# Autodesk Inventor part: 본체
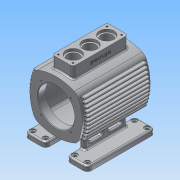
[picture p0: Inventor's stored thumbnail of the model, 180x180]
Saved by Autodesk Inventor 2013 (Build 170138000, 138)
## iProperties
Created: 2015-11
Part Number: 본체
Material: 알루미늄 6061
Document SubType Name: Modeling
Designer: mduedu
Density: 2.71 g/cm^3
Mass: 1542.18 g
Surface Area: 1694.57 cm^2
Volume: 569.07 cm^3
Author: mduedu
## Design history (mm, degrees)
sketch "스케치2"
  geometry: L1 (0, 250)-(0, -250); L2 (250, 0)-(-250, 0); L3 (-50, 50)-(50, 50); L4 (50, 50)-(50, -50); L5 (50, -50)-(-50, -50); L6 (-50, -50)-(-50, 50); A1 r 90 centre (-40, 0) between (40.415, -40.415) and (40.415, 40.415); A2 r 90 centre (40, 0) between (-40.415, 40.415) and (-40.415, -40.415); A3 r 90 centre (0, -40) between (40.415, 40.415) and (-40.415, 40.415); A4 r 90 centre (0, 40) between (-40.415, -40.415) and (40.415, -40.415); 2 further points
  constraints: 12 end point, 8 point on circle, 4 centre point, 4 tangent, 3 perpendicular, 2 horizontal alignment, 2 midpoint, 2 parallel, 2 symmetric about line, 1 coincident, 1 equal radius, 1 horizontal, 1 vertical, 1 vertical alignment, 2 other
  dimensions: "d6" = 500 distance of L1.start L1.end; "d8" = 500 distance of L2.start L2.end; "d9" = 100 distance of L3.end L4.end; "d11" = 90 radius of A3
extrude "돌출1" new body sketch "스케치2" stored distance "d12" = 130; taper "d13" = 0 deg
sketch "스케치3"
  geometry: A1 r 90 centre (40, 0) between (-40.415, 40.415) and (-40.415, -40.415) reference; 2 further points
  constraints: 1 point on circle
fillet "모깎기6" dims "d30" = 15
feature "쉘1" dims "d31" = 15, "d32" = 6, "d33" = 15
sketch "스케치4"
  geometry: L1 (60, -57)-(-60, -57); L2 (-65, 40.415)-(-65, -40.415) reference; L3 (65, -40.415)-(65, 40.415) reference; L4 (-60, -57)-(-60, -45); L5 (60, -57)-(60, -45); L6 (-65, -50)-(65, -50) reference; L7 (-60, -45)-(60, -45); 2 further points
  constraints: 8 end point, 2 parallel, 1 horizontal
  dimensions: "d16" = 5 distance between parallel lines of L7 L6; "d17" = 12 distance of L1.start L5.end; "d23" = 5 distance between parallel lines of L4 L2; "d24" = 5 distance between parallel lines of L5 L3
extrude "돌출2" new body sketch "스케치4" stored distance "d18" = 3; taper "d19" = 0 deg
fillet "모깎기1" dims "d20" = 3
fillet "모깎기4" dims "d25" = 1
sketch "스케치5"
  geometry: C1 r 35 at (0, 0); 1 further point
  constraints: 1 centre point, 1 coincident
  dimensions: "d34" = 70 diameter of C1
extrude "돌출3" cut sketch "스케치5" stored distance "d36" = 3; taper "d37" = 0 deg
feature "결합1"
  node "솔리드2"
fillet "모깎기7" dims "d38" = 1
fillet "모깎기8" dims "d39" = 1
node "작업 평면1"
sketch "스케치6"
  geometry: L1 (-65, -60)-(65, -60); L2 (65, -60)-(65, 60); L3 (65, 60)-(-65, 60); L4 (-65, 60)-(-65, -60); L5 (-65, -60)-(65, 60); L6 (65, -60)-(-65, 60); 1 further point
  constraints: 12 end point, 2 midpoint, 2 parallel, 1 horizontal, 1 perpendicular
  dimensions: "d41" = 120 distance of L3.end L1.start; "d43" = 130 distance of L2.end L3.end
extrude "돌출4" join sketch "스케치6" distance "d44" = 10; taper "d45" = 0 deg
sketch "스케치8"
  geometry: L1 (-60, -70)-(60, -70) reference; L2 (0, -50)-(0, -70); L3 (-30, -44.853)-(-30, -70); L4 (30, -44.853)-(30, -70); L5 (-30, -70)-(30, -70); A1 r 90 centre (0, 40) between (-34.941, -42.941) and (34.941, -42.941) reference; A2 r 90 centre (0, 40) between (-30, -44.853) and (30, -44.853); 1 further point
  constraints: 8 end point, 5 point on circle, 2 perpendicular, 2 symmetric about line, 1 centre point, 1 midpoint, 1 point on line
  dimensions: "d48" = 60 distance between parallel lines of L4 L3
extrude "돌출5" join sketch "스케치8" stored distance "d50" = 80; taper "d51" = 0 deg
sketch "스케치9"
  geometry: L1 (-30, -44.853)-(-30, -70) reference; L2 (30, -70)-(30, -44.853) reference; L3 (-20, -47.75)-(-20, -80); L4 (20, -80)-(20, -47.75); L5 (-48.917, -80)-(48.917, -80) reference; A1 r 90 centre (0, 40) between (-34.941, -42.941) and (34.941, -42.941) reference; 1 further point
  constraints: 4 end point, 2 parallel, 2 point on circle, 2 point on line
  dimensions: "d52" = 10 distance between parallel lines of L2 L4; "d54" = 10 distance between parallel lines of L1 L3 (derived)
extrude "돌출6" cut sketch "스케치9" stored distance "d55" = 80; taper "d56" = 0 deg
fillet "모깎기9" dims "d57" = 8
sketch "스케치10"
  geometry: A1 r 8 centre (-57, 52) between (-57, 60) and (-65, 52) reference; A2 r 8 centre (57, 52) between (65, 52) and (57, 60) reference; A3 r 8 centre (57, 28) between (57, 20) and (65, 28) reference; A4 r 8 centre (-57, 28) between (-65, 28) and (-57, 20) reference; A5 r 8 centre (-57, -28) between (-57, -20) and (-65, -28) reference; A6 r 8 centre (-57, -52) between (-65, -52) and (-57, -60) reference; A7 r 8 centre (57, -52) between (57, -60) and (65, -52) reference; A8 r 8 centre (57, -28) between (65, -28) and (57, -20) reference; 1 further point
hole "구멍1" sketch "스케치10" at (-57, 52), (57, 52), (57, 28), (-57, 28), (-57, -28), (-57, -52), (57, -52), (57, -28) diameter "d58" = 6; stored, may be unused: countersink angle "d62" = 90 deg, drill point angle "d64" = 118 deg; dims "d59" = 6, "d60" = 10, "d61" = 2, "d63" = 8
fillet "모깎기10" dims "d65" = 3
fillet "모깎기11" dims "d66" = 3
fillet "모깎기12" dims "d67" = 3
sketch "스케치11" dims "d72" = 25
  geometry: L1 (65, -50)-(-65, -50) reference; L2 (-80.5, -80)-(80.5, -80) reference; L3 (0, -50)-(0, -80); L4 (-27, -54)-(-10, -54); L5 (-10, -54)-(-10, -62); L6 (-10, -62)-(-27, -62); L7 (-27, -62)-(-27, -54); 3 further points
  constraints: 10 end point, 4 midpoint, 2 parallel, 2 perpendicular, 2 vertical alignment, 1 horizontal, 4 other
  dimensions: "d68" = 8 distance between parallel lines of L6 L4; "d71" = 8 distance from line of point (-27, -58) L1; "d73" = 6 dimension on L3
extrude "돌출7" cut sketch "스케치11" stored distance "d74" = 80; taper "d75" = 0 deg
fillet "모깎기13" dims "d76" = 3
fillet "모깎기14" dims "d78" = 3
sketch "스케치12"
  geometry: L1 (0, 0)-(28.284, 28.284); L2 (0, 0)-(40, 0); A1 r 40 centre (0, 0) between (28.284, 28.284) and (40, 0); 2 further points
  constraints: 4 end point, 2 coincident, 2 point on circle, 1 centre point, 1 horizontal
  dimensions: "d79" = 80 diameter of A1; "d80" = 45 deg angle of L2 L1
hole "구멍2" sketch "스케치12" at (28.284, 28.284) diameter "d82" = 3.242; stored, may be unused: countersink angle "d86" = 90 deg, drill point angle "d88" = 118 deg; dims "d83" = 9, "d84" = 10, "d85" = 2, "d87" = 11
node "작업 평면2"
sketch "스케치13"
  geometry: L1 (-52.5, -20)-(52.5, -20); L2 (52.5, -20)-(52.5, 20); L3 (52.5, 20)-(-52.5, 20); L4 (-52.5, 20)-(-52.5, -20); L5 (-52.5, -20)-(52.5, 20); L6 (52.5, -20)-(-52.5, 20); 1 further point
  constraints: 12 end point, 2 midpoint, 2 parallel, 1 horizontal, 1 perpendicular
  dimensions: "d93" = 105 distance of L2.end L3.end; "d95" = 40 distance of L1.end L2.end
extrude "돌출8" join sketch "스케치13" stored distance "d96" = 80; taper "d97" = 0 deg
fillet "모깎기15" dims "d98" = 5
fillet "모깎기16" dims "d99" = 3
sketch "스케치14"
  geometry: L1 (-52.5, 15)-(-52.5, -15) reference; L2 (52.5, -15)-(52.5, 15) reference; L3 (-52.5, 0)-(52.5, 0); 4 further points
  constraints: 2 end point, 2 midpoint, 2 point on line, 1 coincident
  dimensions: "d100" = 32 distance of point (-32, 0) point (0, 0); "d102" = 32 distance of point (32, 0) point (0, 0) (derived)
hole "구멍3" sketch "스케치14" at (-32, 0), (0, 0), (32, 0) diameter "d103" = 22; stored, may be unused: countersink angle "d107" = 90 deg, drill point angle "d109" = 118 deg; dims "d104" = 8, "d105" = 28, "d106" = 5, "d108" = 10
sketch "스케치15"
  geometry: L1 (46.5, -14)-(-46.5, -14); L2 (-46.5, -14)-(-46.5, 14); L3 (-46.5, 14)-(46.5, 14); L4 (46.5, 14)-(46.5, -14); L5 (46.5, -14)-(-46.5, 14); L6 (-46.5, -14)-(46.5, 14); L7 (47.5, 20)-(-47.5, 20) reference; L8 (-52.5, 15)-(-52.5, -15) reference; 5 further points
  constraints: 12 end point, 4 coincident, 2 midpoint, 2 parallel, 1 horizontal, 1 perpendicular
  dimensions: "d110" = 6 distance between parallel lines of L3 L7; "d111" = 6 distance between parallel lines of L2 L8
hole "구멍4" sketch "스케치15" at (-46.5, 14), (46.5, 14), (46.5, -14), (-46.5, -14) diameter "d112" = 3.242; stored, may be unused: countersink angle "d116" = 90 deg, drill point angle "d118" = 118 deg; dims "d113" = 10, "d114" = 28, "d115" = 5, "d117" = 13
sketch "스케치16"
  geometry: L1 (33.5, 0)-(61.5, 0) reference; L2 (104.5, -150)-(-9.5, -150) reference; L3 (47.5, 0)-(47.5, -150); 2 further points
  constraints: 2 end point, 2 midpoint, 1 point on line, 1 other
  dimensions: "d122" = 11 distance from line of point (47.5, -11) L1
feature "엠보싱2" sketch "스케치16" dims "d16" = 5, "d17" = 12, "d23" = 5, "d24" = 5, "d123" = 0.5, "d124" = 0
chamfer "모따기1" distance "d125" = 1; stored, may be unused: second distance "d126" = 2, angle "d127" = 45 deg
node "솔리드1"
pattern_linear "직사각형 패턴1" dims "d29" = 7
mirror "대칭1"
mirror "대칭2"
pattern_circular "원형 패턴1" dims angle "d90" = 360 deg
mirror "대칭3"
